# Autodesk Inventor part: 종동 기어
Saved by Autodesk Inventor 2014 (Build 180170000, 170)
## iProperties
Created: 2026-04
Part Number: 종동 기어
Material: 강철, 탄소
Document SubType Name: Modeling
Designer: dg
Density: 7.87 g/cm^3
Appearance: 반연마
Mass: 421.879 g
Surface Area: 238.706 cm^2
Volume: 53.6059 cm^3
Author: jhkim
Creation Date: 2026-03-27
Sending System: Autodesk Inventor 2026
Preprocessor: ST-DEVELOPER v20.1
Author: dg
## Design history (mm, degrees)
node "종동 기어1"
node "솔리드1"
node "기준1"
